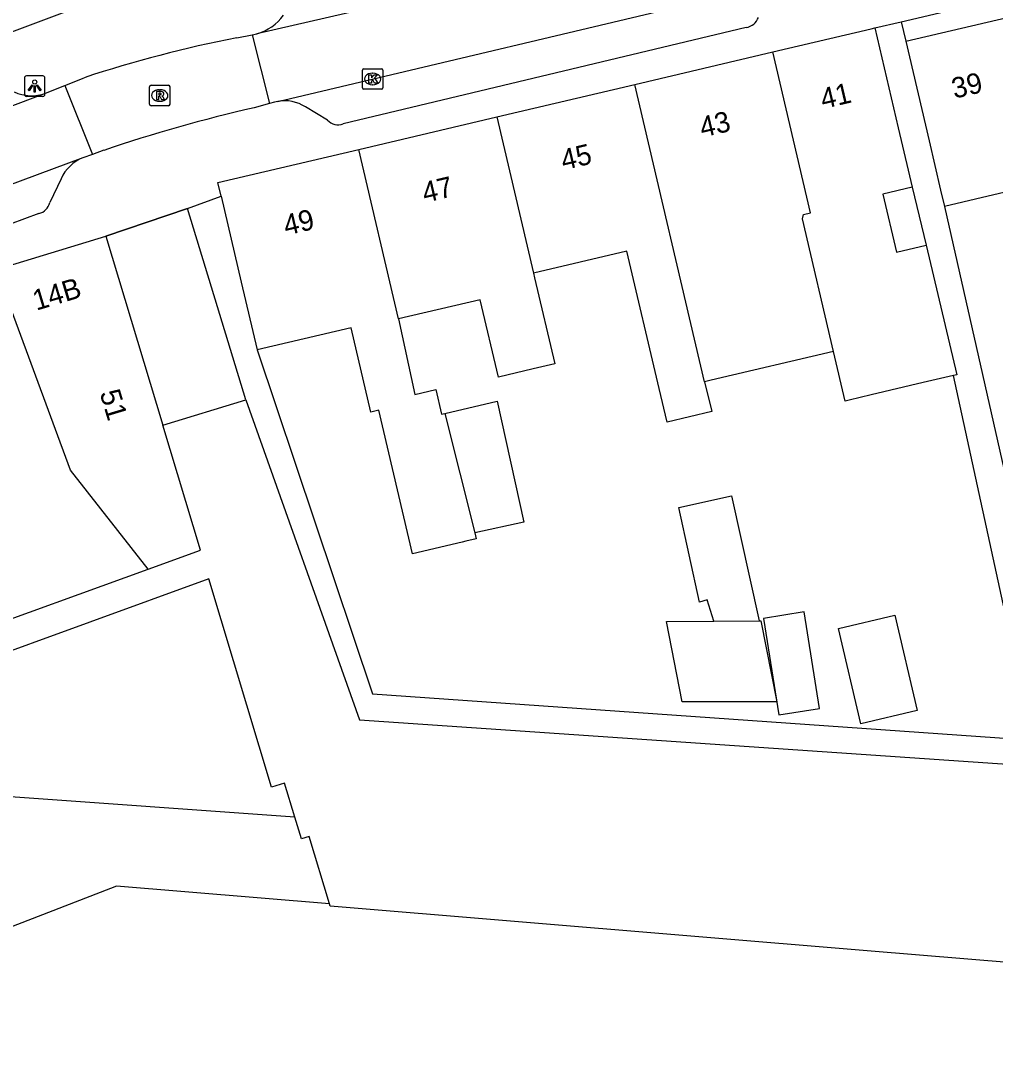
# Model space of a CAD drawing. Extents: x 160861 to 161308, y 384024 to 384878.
# Drawn here: x 160958.5 to 161006.1, y 384646.2 to 384696.7 of the extents above; entities that cross this region are included whole.
import ezdxf

# ---------------------------------------------------------------- set-up
doc = ezdxf.new("R2010")
doc.units = 0
for name, color, linetype in [('IMGEO_Kolk', 7, 'Continuous'), ('IMGEO_Lichtpunt', 7, 'Continuous'), ('IMGEO_Pand', 7, 'Continuous'), ('IMGEO_Pand_nummerreeks', 7, 'Continuous'), ('IMGEO_Pand_overbouw', 7, 'Continuous'), ('IMGEO_Rijbaan_lokaal_open', 7, 'Continuous'), ('IMGEO_Rioolput', 7, 'Continuous'), ('IMGEO_Voetpad_open', 7, 'Continuous')]:
    doc.layers.add(name, color=color, linetype=linetype)

msp = doc.modelspace()

# ---------------------------------------------------------------- linework, layer by layer
at = {"layer": 'IMGEO_Kolk'}
for p, q in [((160975.16, 384693.465), (160975.16, 384694.317)), ((160975.235, 384694.391), (160976.087, 384694.391)), ((160976.161, 384694.317), (160976.161, 384693.465)), ((160975.648, 384694.171), (160975.673, 384694.171)), ((160976.087, 384693.391), (160975.235, 384693.391)), ((160975.671, 384693.611), (160975.646, 384693.611))]:
    msp.add_line(p, q, dxfattribs=at)
for points in [[(160975.16, 384693.465), (160975.16, 384694.317)], [(160975.235, 384694.391), (160976.087, 384694.391)], [(160976.161, 384694.317), (160976.161, 384693.465)], [(160975.481, 384694.091), (160975.604, 384694.091), (160975.604, 384693.94), (160975.734, 384694.091), (160975.898, 384694.091), (160975.752, 384693.94), (160975.905, 384693.691), (160975.753, 384693.691), (160975.668, 384693.855), (160975.604, 384693.788), (160975.604, 384693.691), (160975.481, 384693.691), (160975.481, 384694.091)], [(160976.087, 384693.391), (160975.235, 384693.391)]]:
    msp.add_lwpolyline(points, dxfattribs=at)
for centre, start, end in [((160975.237, 384694.315), 91.552, 178.448), ((160975.237, 384694.315), 91.552, 178.448), ((160976.085, 384694.315), 1.552, 88.448), ((160976.085, 384694.315), 1.552, 88.448), ((160975.237, 384693.467), 181.552, 268.448), ((160975.237, 384693.467), 181.552, 268.448), ((160976.085, 384693.467), 271.552, 358.448), ((160976.085, 384693.467), 271.552, 358.448)]:
    msp.add_arc(centre, 0.0765, start, end, dxfattribs=at)
for centre, major_axis, ratio, start_param, end_param in [((160975.647, 384693.891), (-0.387, 0.002), 0.722429, 4.712389, 7.853982), ((160975.672, 384693.891), (-0.39, 0.002), 0.717154, 1.570796, 4.712389)]:
    msp.add_ellipse(centre, major_axis=major_axis, ratio=ratio, start_param=start_param, end_param=end_param, dxfattribs=at)
at = {"layer": 'IMGEO_Lichtpunt'}
for p, q in [((160958.657, 384693.945), (160958.657, 384693.138)), ((160958.657, 384693.945), (160958.657, 384693.138)), ((160959.559, 384694.04), (160958.751, 384694.04)), ((160959.559, 384694.04), (160958.751, 384694.04)), ((160959.653, 384693.138), (160959.653, 384693.945)), ((160959.653, 384693.138), (160959.653, 384693.945)), ((160958.751, 384693.044), (160959.559, 384693.044)), ((160958.751, 384693.044), (160959.559, 384693.044))]:
    msp.add_line(p, q, dxfattribs=at)
for points in [[(160959.031, 384693.609), (160959.07, 384693.581), (160958.882, 384693.319), (160958.844, 384693.346), (160959.031, 384693.609)], [(160959.133, 384693.561), (160959.18, 384693.561), (160959.18, 384693.239), (160959.133, 384693.239), (160959.133, 384693.561)], [(160959.243, 384693.581), (160959.281, 384693.608), (160959.468, 384693.346), (160959.429, 384693.318), (160959.243, 384693.581)]]:
    msp.add_lwpolyline(points, dxfattribs=at)
msp.add_circle((160959.156, 384693.743), 0.0994, dxfattribs=at)
for centre, start, end in [((160958.751, 384693.945), 90, 180), ((160958.751, 384693.945), 90, 180), ((160959.559, 384693.945), 0, 90), ((160959.559, 384693.945), 0, 90), ((160958.751, 384693.138), 180, 270), ((160958.751, 384693.138), 180, 270), ((160959.559, 384693.138), 270, 0), ((160959.559, 384693.138), 270, 360)]:
    msp.add_arc(centre, 0.0946, start, end, dxfattribs=at)
at = {"layer": 'IMGEO_Pand'}
for points in [[(160954.629, 384694.918), (160962.721, 384697.973), (160962.66, 384698.215)], [(161001.694, 384695.742), (161006.641, 384696.888)], [(160995.201, 384695.209), (161000, 384696.338), (161000.184, 384696.381)], [(161000.184, 384696.381), (161001.329, 384691.514), (161001.815, 384689.447), (161002.012, 384688.611)], [(161001.694, 384695.742), (161002.833, 384690.874), (161003.397, 384688.464), (161003.583, 384687.669)], [(160988.461, 384693.623), (160995.201, 384695.209)], [(160998.171, 384680.595), (160996.648, 384687.069), (160996.704, 384687.269), (160997.049, 384687.351), (160995.201, 384695.209)], [(160981.722, 384692.037), (160988.461, 384693.623)], [(160991.874, 384679.113), (160988.461, 384693.623)], [(160974.983, 384690.451), (160981.722, 384692.037)], [(160981.722, 384692.037), (160983.515, 384684.412)], [(160968.254, 384688.176), (160968.1, 384688.831), (160974.983, 384690.451)], [(160976.93, 384682.175), (160974.983, 384690.451)], [(161008.509, 384688.823), (161005.999, 384688.235), (161003.583, 384687.669)], [(160968.254, 384688.176), (160969.245, 384683.965), (160970.021, 384680.67)], [(161002.012, 384688.611), (161000.575, 384688.273), (161001.242, 384685.441), (161002.696, 384685.783)], [(160957.27, 384684.595), (160962.626, 384686.212)], [(160962.626, 384686.212), (160965.408, 384676.997)], [(161002.696, 384685.783), (161004.186, 384679.453), (161004.02, 384679.414)], [(160991.874, 384679.113), (160992.217, 384677.658), (160990.038, 384677.145), (160989.651, 384678.79), (160988.075, 384685.485), (160983.515, 384684.412)], [(160964.692, 384669.97), (160960.908, 384674.794), (160957.27, 384684.595)], [(160983.515, 384684.412), (160983.57, 384684.179), (160984.556, 384679.985), (160983.504, 384679.737), (160981.806, 384679.337), (160980.917, 384683.113), (160976.93, 384682.175)], [(160976.93, 384682.175), (160977.718, 384678.488), (160978.741, 384678.728), (160979.023, 384677.53), (160979.186, 384677.568)], [(160980.648, 384671.734), (160980.72, 384671.445), (160980.215, 384671.326), (160980.024, 384671.281), (160977.607, 384670.712), (160975.957, 384677.724), (160975.573, 384677.634), (160974.604, 384681.749), (160970.021, 384680.67)], [(160998.171, 384680.595), (160992.192, 384679.188), (160991.874, 384679.113)], [(161004.02, 384679.414), (161002.543, 384679.067), (161000, 384678.469), (160998.938, 384678.218), (160998.741, 384678.172), (160998.171, 384680.595)], [(160979.186, 384677.568), (160981.734, 384678.168), (160983.036, 384672.261), (160980.648, 384671.734)], [(160979.186, 384677.568), (160980.648, 384671.734)], [(160964.692, 384669.97), (160967.25, 384670.899), (160965.408, 384676.997)], [(160992.33, 384667.423), (160992.004, 384668.473), (160991.617, 384668.353), (160990.607, 384672.979), (160993.183, 384673.541), (160994.53, 384667.441)], [(160955.594, 384666.434), (160955.52, 384666.637), (160964.692, 384669.97)], [(160971.859, 384657.86), (160971.358, 384659.52), (160970.725, 384659.329), (160967.658, 384669.485), (160956.022, 384665.257), (160955.594, 384666.434)], [(160994.53, 384667.441), (160994.623, 384667.442), (160995.394, 384663.493), (160990.769, 384663.493), (160990.017, 384667.404), (160992.33, 384667.423)], [(160992.33, 384667.423), (160994.53, 384667.441)], [(160997.48, 384663.165), (160996.735, 384667.873), (160994.752, 384667.559), (160995.497, 384662.851), (160997.48, 384663.165)], [(161001.159, 384667.714), (161002.246, 384663.058), (160999.496, 384662.417), (160998.409, 384667.072), (161001.159, 384667.714)], [(160971.859, 384657.86), (160957.517, 384658.886), (160945.078, 384656.249), (160937.451, 384653.082)], [(160973.559, 384653.621), (160972.563, 384656.918), (160972.179, 384656.802), (160971.859, 384657.86)], [(160973.559, 384653.621), (160963.147, 384654.482), (160948.047, 384648.651), (160947.852, 384649.157), (160940.157, 384646.186)], [(161011.607, 384650.352), (161000, 384651.318), (160973.59, 384653.518), (160973.559, 384653.621)]]:
    msp.add_lwpolyline(points, dxfattribs=at)
at = {"layer": 'IMGEO_Pand_overbouw'}
msp.add_lwpolyline([(160965.408, 384676.997), (160969.466, 384678.232), (160968.085, 384682.767), (160966.621, 384687.573), (160962.626, 384686.212)], close=True, dxfattribs=at)
at = {"layer": 'IMGEO_Rijbaan_lokaal_open'}
for points in [[(160984.769, 384699.502), (160970.01, 384696.102)], [(160971.03, 384692.792), (160993.576, 384698.147)], [(160969.031, 384695.9), (160969.772, 384696.053)], [(160969.772, 384696.053), (160970.01, 384696.102)], [(160969.772, 384696.053), (160970.624, 384692.689)], [(160960.623, 384693.571), (160961.573, 384693.953)], [(160959.689, 384693.195), (160960.623, 384693.571)], [(160960.623, 384693.571), (160961.975, 384690.212)], [(160928.722, 384681.501), (160959.689, 384693.195)], [(160971.03, 384692.792), (160970.861, 384692.752), (160970.624, 384692.689)], [(160970.624, 384692.689), (160969.878, 384692.489)], [(160961.975, 384690.212), (160961.512, 384690.047)], [(160962.526, 384690.408), (160961.975, 384690.212)], [(160961.512, 384690.047), (160947.406, 384684.802)], [(160962.626, 384686.212), (160966.621, 384687.573)], [(160969.466, 384678.232), (160968.085, 384682.767), (160966.621, 384687.573)], [(160965.408, 384676.997), (160969.466, 384678.232)]]:
    msp.add_lwpolyline(points, dxfattribs=at)
for centre, radius, start, end in [((160980.724, 384635.853), 61.175, 101.01919, 108.2432), ((160987.298, 384616.919), 77.551, 102.98057, 108.62799)]:
    msp.add_arc(centre, radius, start, end, dxfattribs=at)
at = {"layer": 'IMGEO_Rioolput'}
for p, q in [((160964.762, 384692.658), (160964.762, 384693.51)), ((160964.837, 384693.584), (160965.689, 384693.584)), ((160965.25, 384693.364), (160965.275, 384693.364)), ((160965.763, 384693.51), (160965.763, 384692.658)), ((160965.273, 384692.804), (160965.248, 384692.804)), ((160965.689, 384692.584), (160964.837, 384692.584))]:
    msp.add_line(p, q, dxfattribs=at)
for points in [[(160964.762, 384692.658), (160964.762, 384693.51)], [(160964.837, 384693.584), (160965.689, 384693.584)], [(160965.351, 384693.282), (160965.099, 384693.284), (160965.099, 384692.884)], [(160965.763, 384693.51), (160965.763, 384692.658)], [(160965.099, 384692.884), (160965.223, 384692.884), (160965.223, 384693.046), (160965.234, 384693.046)], [(160965.277, 384693.203), (160965.223, 384693.203), (160965.223, 384693.122)], [(160965.223, 384693.122), (160965.275, 384693.122)], [(160965.281, 384693.017), (160965.352, 384692.884), (160965.492, 384692.884), (160965.427, 384693.01)], [(160965.689, 384692.584), (160964.837, 384692.584)]]:
    msp.add_lwpolyline(points, dxfattribs=at)
for centre, radius, start, end in [((160964.839, 384693.508), 0.0765, 91.552, 178.448), ((160964.839, 384693.508), 0.0765, 91.552, 178.448), ((160965.35, 384693.172), 0.109, 350.3612, 89.416), ((160965.687, 384693.508), 0.0765, 1.552, 88.448), ((160965.687, 384693.508), 0.0765, 1.552, 88.448), ((160965.233, 384692.993), 0.0533, 26.0293, 88.6989), ((160965.259, 384693.311), 0.19, 274.7715, 282.9687), ((160965.283, 384693.107), 0.0964, 77.0061, 93.1865), ((160965.297, 384693.164), 0.0378, 276.6634, 79.6772), ((160965.348, 384693.172), 0.112, 277.5842, 350.9817), ((160965.332, 384692.957), 0.108, 29.5134, 73.7905), ((160964.839, 384692.66), 0.0765, 181.552, 268.448), ((160964.839, 384692.66), 0.0765, 181.552, 268.448), ((160965.687, 384692.66), 0.0765, 271.552, 358.448), ((160965.687, 384692.66), 0.0765, 271.552, 358.448)]:
    msp.add_arc(centre, radius, start, end, dxfattribs=at)
for centre, major_axis, ratio, start_param, end_param in [((160965.249, 384693.084), (-0.387, 0.002), 0.722429, 4.712389, 7.853982), ((160965.274, 384693.084), (-0.39, 0.002), 0.717154, 1.570796, 4.712389)]:
    msp.add_ellipse(centre, major_axis=major_axis, ratio=ratio, start_param=start_param, end_param=end_param, dxfattribs=at)
at = {"layer": 'IMGEO_Voetpad_open'}
for points in [[(161001.472, 384696.684), (161020.098, 384701.072), (161019.614, 384709.69)], [(160993.906, 384696.398), (160974.221, 384691.696)], [(161000.184, 384696.381), (161001.472, 384696.684)], [(161001.472, 384696.684), (161001.694, 384695.742)], [(160973.45, 384691.885), (160972.379, 384692.531)], [(160960.449, 384689.023), (160959.892, 384687.854)], [(160966.621, 384687.573), (160968.254, 384688.176)], [(161002.012, 384688.611), (161002.696, 384685.783)], [(161003.583, 384687.669), (161009.497, 384661.544), (161027.455, 384660.754)], [(160959.364, 384687.32), (160950.948, 384684.202)], [(160970.021, 384680.67), (160975.646, 384663.885), (161007.907, 384661.614), (161004.02, 384679.414)], [(160969.466, 384678.232), (160975.017, 384662.612), (161012.363, 384660.051)]]:
    msp.add_lwpolyline(points, dxfattribs=at)
for centre, radius, start, end in [((160969.389, 384698.355), 2.337, 285.4036, 324.8009), ((160993.749, 384697.198), 0.815, 281.0897, 338.1824), ((160959, 384695.046), 1.974, 244.4573, 290.4119), ((160971.377, 384690.971), 1.854, 57.2999, 100.7999), ((160973.975, 384692.358), 0.706, 222.0238, 290.4288), ((160962.224, 384688.245), 1.938, 111.5427, 156.3162), ((160959.176, 384688.034), 0.739, 284.7767, 345.8707)]:
    msp.add_arc(centre, radius, start, end, dxfattribs=at)

# ---------------------------------------------------------------- texts
at = {"layer": 'IMGEO_Pand_nummerreeks'}
for s, rotation, p in [('39', 13.0412, (161004.067, 384692.926)), ('41', 13.2411, (160997.657, 384692.417)), ('43', 13.2411, (160991.759, 384691.028)), ('45', 13.2411, (160984.984, 384689.434)), ('47', 13.2411, (160978.209, 384687.84)), ('49', 13.2411, (160971.434, 384686.245)), ('14B', 16.7993, (160959.235, 384682.577)), ('51', 286.799, (160962.322, 384678.569))]:
    msp.add_text(s, height=1, rotation=rotation, dxfattribs=at).set_placement(p)

doc.saveas('drawing.dxf')
